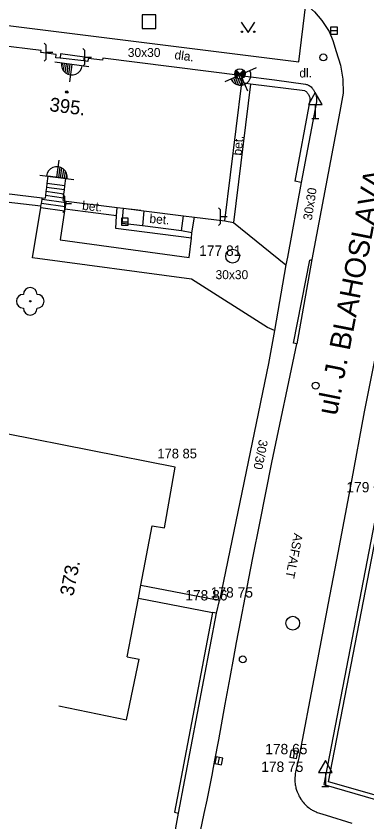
# Model space of a CAD drawing. Extents: x -538441 to -536770, y -1181008 to -1179809.
# Drawn here: x -537929.5 to -537904.1, y -1180678.1 to -1180619.8 of the extents above; entities that cross this region are included whole.
import ezdxf

# ---------------------------------------------------------------- set-up
doc = ezdxf.new("R2010")
doc.units = 0
for name, color, linetype in [('Vrstva 10', 7, 'Continuous'), ('Vrstva 11', 7, 'Continuous'), ('Vrstva 17', 7, 'Continuous'), ('Vrstva 22', 7, 'Continuous'), ('Vrstva 26', 7, 'Continuous'), ('Vrstva 27', 7, 'Continuous'), ('Vrstva 28', 7, 'Continuous'), ('Vrstva 31', 7, 'Continuous'), ('Vrstva 34', 7, 'Continuous'), ('Vrstva 36', 7, 'Continuous'), ('Vrstva 37', 7, 'Continuous'), ('Vrstva 39', 7, 'Continuous'), ('Vrstva 4', 7, 'Continuous'), ('Vrstva 40', 7, 'Continuous'), ('Vrstva 47', 7, 'Continuous'), ('Vrstva 49', 7, 'Continuous'), ('Vrstva 5', 7, 'Continuous'), ('Vrstva 6', 7, 'Continuous'), ('Vrstva 7', 7, 'Continuous'), ('Vrstva 8', 7, 'Continuous')]:
    doc.layers.add(name, color=color, linetype=linetype)

msp = doc.modelspace()

# ---------------------------------------------------------------- linework, layer by layer
at = {"layer": 'Vrstva 10'}
for p, q in [((-537905.81, -1180625.34), (-537906.04, -1180626.67)), ((-537906.04, -1180626.67), (-537908.08, -1180637.38)), ((-537909.41, -1180643.45), (-537908.22, -1180637.43)), ((-537908.08, -1180637.38), (-537909.16, -1180643.49)), ((-537908.22, -1180637.43), (-537908.08, -1180637.38)), ((-537902.05, -1180637.145), (-537904.27, -1180648.43)), ((-537910.975, -1180652.088), (-537909.16, -1180643.49)), ((-537909.16, -1180643.49), (-537909.41, -1180643.45)), ((-537904.27, -1180648.43), (-537905.23, -1180653.525)), ((-537905.23, -1180653.525), (-537906.19, -1180658.62)), ((-537906.19, -1180658.62), (-537906.88, -1180662.271)), ((-537912.91, -1180661.87), (-537912.347, -1180658.997)), ((-537906.88, -1180662.271), (-537907.919, -1180667.746)), ((-537907.919, -1180667.746), (-537908.96, -1180673.22)), ((-537914.825, -1180672.169), (-537914.351, -1180669.593))]:
    msp.add_line(p, q, dxfattribs=at)
for points in [[(-537908.51, -1180618.89), (-537907.885, -1180619.439), (-537907.342, -1180620.069), (-537906.82, -1180620.88), (-537906.542, -1180621.524), (-537906.3, -1180622.32)], [(-537906.3, -1180622.32), (-537905.998, -1180623.301), (-537905.834, -1180624.314), (-537905.81, -1180625.34)], [(-537912.347, -1180658.997), (-537911.851, -1180656.484), (-537910.975, -1180652.088)], [(-537914.351, -1180669.593), (-537913.997, -1180667.661), (-537913.731, -1180666.212), (-537913.529, -1180665.126), (-537913.223, -1180663.497), (-537912.91, -1180661.87)], [(-537916.52, -1180680.52), (-537916.15, -1180678.802), (-537915.877, -1180677.514), (-537915.676, -1180676.547), (-537915.527, -1180675.821), (-537915.31, -1180674.731), (-537915.204, -1180674.186), (-537915.1, -1180673.64), (-537914.825, -1180672.169)], [(-537908.96, -1180673.22), (-537908.992, -1180673.381), (-537909.056, -1180673.661), (-537909.157, -1180674.081), (-537909.205, -1180674.29), (-537909.25, -1180674.5), (-537909.275, -1180674.645), (-537909.292, -1180674.781), (-537909.302, -1180674.908), (-537909.306, -1180675.027), (-537909.304, -1180675.139), (-537909.298, -1180675.243), (-537909.288, -1180675.341), (-537909.275, -1180675.433), (-537909.26, -1180675.519), (-537909.243, -1180675.6), (-537909.225, -1180675.675), (-537909.205, -1180675.746), (-537909.184, -1180675.812), (-537909.14, -1180675.936), (-537909.096, -1180676.043), (-537909.052, -1180676.138), (-537909.01, -1180676.22), (-537908.971, -1180676.292), (-537908.934, -1180676.355), (-537908.866, -1180676.464), (-537908.81, -1180676.546), (-537908.765, -1180676.607), (-537908.695, -1180676.699), (-537908.62, -1180676.79), (-537908.575, -1180676.842), (-537908.531, -1180676.889), (-537908.488, -1180676.933), (-537908.404, -1180677.011), (-537908.324, -1180677.078), (-537908.249, -1180677.136), (-537908.177, -1180677.185), (-537908.109, -1180677.228), (-537908.045, -1180677.265), (-537907.985, -1180677.297), (-537907.87, -1180677.352), (-537907.768, -1180677.396), (-537907.679, -1180677.43), (-537907.519, -1180677.485), (-537907.275, -1180677.56), (-537907.026, -1180677.635), (-537905.175, -1180678.209)]]:
    msp.add_lwpolyline(points, dxfattribs=at)
at = {"layer": 'Vrstva 11'}
for p, q in [((-537944.15, -1180618.63), (-537924.88, -1180621.1)), ((-537909.01, -1180623.06), (-537908.51, -1180618.89)), ((-537924.88, -1180621.1), (-537909.01, -1180623.06)), ((-537912.526, -1180624.676), (-537913.75, -1180634.71)), ((-537908.84, -1180631.81), (-537909.85, -1180637.22)), ((-537927.724, -1180633.532), (-537939.86, -1180632.06)), ((-537926.024, -1180632.345), (-537927.323, -1180632.166)), ((-537925.988, -1180632.048), (-537927.287, -1180631.869)), ((-537926.098, -1180632.94), (-537927.397, -1180632.761)), ((-537926.061, -1180632.643), (-537927.36, -1180632.464)), ((-537925.968, -1180633.564), (-537927.69, -1180633.327)), ((-537925.917, -1180633.269), (-537927.641, -1180633.031)), ((-537927.739, -1180633.623), (-537926.02, -1180633.86)), ((-537926.02, -1180633.86), (-537926.32, -1180635.97)), ((-537922.231, -1180634.227), (-537926, -1180633.747)), ((-537920.257, -1180633.854), (-537920.365, -1180634.958)), ((-537917.52, -1180635.32), (-537917.378, -1180634.215)), ((-537916.79, -1180635.46), (-537916.596, -1180634.313)), ((-537914.39, -1180634.59), (-537913.75, -1180634.71)), ((-537913.75, -1180634.71), (-537909.948, -1180637.782)), ((-537916.81, -1180635.85), (-537922.28, -1180635.13)), ((-537916.79, -1180635.46), (-537917.52, -1180635.32)), ((-537916.98, -1180637.23), (-537916.81, -1180635.85)), ((-537916.81, -1180635.85), (-537916.79, -1180635.46)), ((-537926.32, -1180635.97), (-537916.98, -1180637.23)), ((-537916.8, -1180638.8), (-537928.34, -1180637.26)), ((-537911.3, -1180642.3), (-537916.8, -1180638.8)), ((-537910.78, -1180642.53), (-537911.3, -1180642.3)), ((-537910.78, -1180642.53), (-537911.22, -1180644.92)), ((-537911.22, -1180644.92), (-537914.76, -1180662.08)), ((-537920.478, -1180660.973), (-537915.054, -1180662.022)), ((-537920.659, -1180661.913), (-537915.275, -1180662.954))]:
    msp.add_line(p, q, dxfattribs=at)
for points in [[(-537924.602, -1180623.002), (-537924.57, -1180622.72), (-537926.3, -1180622.5), (-537926.335, -1180622.806)], [(-537928.34, -1180637.26), (-537927.739, -1180633.623), (-537927.724, -1180633.532), (-537927.69, -1180633.327), (-537927.641, -1180633.031), (-537927.624, -1180632.925)], [(-537925.896, -1180633.148), (-537925.917, -1180633.269), (-537925.968, -1180633.564), (-537926, -1180633.747), (-537926.02, -1180633.86)], [(-537922.28, -1180635.13), (-537922.231, -1180634.227), (-537922.198, -1180633.611)], [(-537917.52, -1180635.32), (-537920.365, -1180634.958), (-537921.84, -1180634.77), (-537921.728, -1180633.67)], [(-537909.85, -1180637.22), (-537909.948, -1180637.782), (-537910.78, -1180642.53)]]:
    msp.add_lwpolyline(points, dxfattribs=at)
at = {"layer": 'Vrstva 17'}
for p, q in [((-537913.664, -1180623.961), (-537913.467, -1180623.763)), ((-537913.661, -1180623.887), (-537913.502, -1180623.728)), ((-537913.656, -1180624.023), (-537913.431, -1180623.799)), ((-537913.639, -1180624.077), (-537913.396, -1180623.834)), ((-537913.633, -1180623.788), (-537913.537, -1180623.693)), ((-537913.616, -1180624.125), (-537913.361, -1180623.869)), ((-537913.588, -1180624.167), (-537913.325, -1180623.905)), ((-537913.555, -1180624.205), (-537913.025, -1180623.675)), ((-537913.555, -1180623.675), (-537913.025, -1180624.205)), ((-537913.255, -1180623.975), (-537912.992, -1180623.713)), ((-537913.219, -1180624.011), (-537912.964, -1180623.755)), ((-537913.184, -1180624.046), (-537912.941, -1180623.803)), ((-537913.149, -1180624.081), (-537912.924, -1180623.857)), ((-537913.113, -1180624.117), (-537912.916, -1180623.919)), ((-537913.078, -1180624.152), (-537912.919, -1180623.993)), ((-537913.043, -1180624.187), (-537912.947, -1180624.092))]:
    msp.add_line(p, q, dxfattribs=at)
msp.add_circle((-537913.29, -1180623.94), 0.375, dxfattribs=at)
at = {"layer": 'Vrstva 22'}
msp.add_circle((-537928.5, -1180640.41), 0.05, dxfattribs=at)
for centre, start, end in [((-537928.5, -1180639.91), 0, 180), ((-537929, -1180640.41), 90, 270), ((-537928, -1180640.41), 270, 90), ((-537928.5, -1180640.91), 180, 0)]:
    msp.add_arc(centre, 0.5, start, end, dxfattribs=at)
at = {"layer": 'Vrstva 26'}
msp.add_lwpolyline([(-537920.39, -1180620.66), (-537919.39, -1180620.66), (-537919.39, -1180619.66), (-537920.39, -1180619.66)], close=True, dxfattribs=at)
at = {"layer": 'Vrstva 27'}
for p, q in [((-537906.71, -1180620.81), (-537906.21, -1180620.81)), ((-537927.48, -1180621.728), (-537927.338, -1180621.87)), ((-537927.338, -1180622.87), (-537927.338, -1180621.87)), ((-537927.338, -1180622.37), (-537926.85, -1180622.37)), ((-537924.69, -1180622.098), (-537924.548, -1180622.24)), ((-537924.548, -1180623.24), (-537924.548, -1180622.24)), ((-537927.48, -1180623.01), (-537927.338, -1180622.87)), ((-537924.548, -1180622.74), (-537924.06, -1180622.74)), ((-537924.69, -1180623.38), (-537924.548, -1180623.24)), ((-537926.14, -1180632.688), (-537925.998, -1180632.83)), ((-537925.998, -1180633.83), (-537925.998, -1180632.83)), ((-537925.998, -1180633.33), (-537925.51, -1180633.33)), ((-537926.14, -1180633.97), (-537925.998, -1180633.83)), ((-537914.85, -1180633.638), (-537914.708, -1180633.78)), ((-537914.708, -1180634.78), (-537914.708, -1180633.78)), ((-537921.89, -1180634.65), (-537921.39, -1180634.65)), ((-537914.708, -1180634.28), (-537914.22, -1180634.28)), ((-537914.85, -1180634.92), (-537914.708, -1180634.78)), ((-537909.338, -1180672.978), (-537909.432, -1180673.47)), ((-537914.868, -1180673.94), (-537914.774, -1180673.45))]:
    msp.add_line(p, q, dxfattribs=at)
for points in [[(-537906.71, -1180621.06), (-537906.21, -1180621.06), (-537906.21, -1180620.56), (-537906.71, -1180620.56)], [(-537921.89, -1180634.9), (-537921.39, -1180634.9), (-537921.39, -1180634.4), (-537921.89, -1180634.4)], [(-537909.584, -1180672.932), (-537909.677, -1180673.423), (-537909.186, -1180673.516), (-537909.093, -1180673.025)], [(-537914.623, -1180673.988), (-537914.528, -1180673.497), (-537915.019, -1180673.402), (-537915.114, -1180673.893)]]:
    msp.add_lwpolyline(points, close=True, dxfattribs=at)
for centre in [(-537913.82, -1180637.14), (-537909.46, -1180663.73)]:
    msp.add_circle(centre, 0.5, dxfattribs=at)
at = {"layer": 'Vrstva 28'}
for centre in [(-537907.79, -1180646.52), (-537913.08, -1180666.35)]:
    msp.add_circle(centre, 0.25, dxfattribs=at)
at = {"layer": 'Vrstva 31'}
msp.add_circle((-537907.24, -1180622.75), 0.25, dxfattribs=at)
at = {"layer": 'Vrstva 34'}
for p, q in [((-537907.824, -1180626.156), (-537907.824, -1180627.174)), ((-537908.074, -1180627.174), (-537907.574, -1180627.174)), ((-537907.09, -1180674.541), (-537907.09, -1180675.559)), ((-537907.34, -1180675.559), (-537906.84, -1180675.559))]:
    msp.add_line(p, q, dxfattribs=at)
for points in [[(-537908.324, -1180626.156), (-537907.324, -1180626.156), (-537907.824, -1180625.29)], [(-537907.59, -1180674.541), (-537906.59, -1180674.541), (-537907.09, -1180673.675)]]:
    msp.add_lwpolyline(points, close=True, dxfattribs=at)
at = {"layer": 'Vrstva 36'}
msp.add_lwpolyline([(-537913.199, -1180620.189), (-537912.699, -1180620.939), (-537912.199, -1180620.189)], dxfattribs=at)
for centre in [(-537913.149, -1180620.889), (-537912.25, -1180620.889)]:
    msp.add_circle(centre, 0.05, dxfattribs=at)
at = {"layer": 'Vrstva 37'}
for p, q in [((-537924.248, -1180623.427), (-537926.726, -1180623.103)), ((-537926.181, -1180623.174), (-537926.217, -1180623.451)), ((-537926.043, -1180623.192), (-537926.109, -1180623.695)), ((-537925.903, -1180623.211), (-537925.985, -1180623.835)), ((-537925.765, -1180623.229), (-537925.856, -1180623.927)), ((-537925.625, -1180623.247), (-537925.721, -1180623.986)), ((-537925.487, -1180623.265), (-537925.65, -1180624.511)), ((-537912.104, -1180623.51), (-537914.396, -1180624.51)), ((-537913.763, -1180624.234), (-537913.56, -1180624.699)), ((-537913.635, -1180624.178), (-537913.383, -1180624.755)), ((-537913.507, -1180624.122), (-537913.225, -1180624.767)), ((-537913.378, -1180624.066), (-537913.08, -1180624.749)), ((-537913.25, -1180624.01), (-537912.747, -1180625.163)), ((-537913.892, -1180624.29), (-537913.78, -1180624.545)), ((-537926.572, -1180631.427), (-537926.409, -1180630.181)), ((-537926.434, -1180631.445), (-537926.338, -1180630.706)), ((-537926.294, -1180631.463), (-537926.203, -1180630.765)), ((-537926.156, -1180631.481), (-537926.074, -1180630.857)), ((-537926.016, -1180631.5), (-537925.95, -1180630.997)), ((-537925.878, -1180631.518), (-537925.842, -1180631.241)), ((-537927.811, -1180631.265), (-537925.333, -1180631.589))]:
    msp.add_line(p, q, dxfattribs=at)
for centre, start, end in [((-537925.488, -1180623.273), 171.92788, 353.17392), ((-537913.247, -1180624.017), 202.95771, 24.20376), ((-537926.571, -1180631.419), 351.92788, 173.17392)]:
    msp.add_arc(centre, 0.75, start, end, dxfattribs=at)
at = {"layer": 'Vrstva 39'}
for radius in [0.09, 0.0398]:
    msp.add_circle((-537925.85, -1180625.252), radius, dxfattribs=at)
at = {"layer": 'Vrstva 5'}
for p, q in [((-537927.71, -1180622.25), (-537937.79, -1180621.01)), ((-537927.729, -1180622.404), (-537927.71, -1180622.25)), ((-537926.62, -1180622.54), (-537927.729, -1180622.404)), ((-537926.65, -1180622.77), (-537926.62, -1180622.54)), ((-537924.31, -1180622.82), (-537924.334, -1180623.032)), ((-537923.25, -1180622.94), (-537924.31, -1180622.82)), ((-537923.23, -1180622.8), (-537923.25, -1180622.94)), ((-537913.09, -1180624.07), (-537923.23, -1180622.8)), ((-537925.922, -1180631.512), (-537927.222, -1180631.342)), ((-537917.98, -1180652.42), (-537930.21, -1180650)), ((-537918.76, -1180656.83), (-537917.98, -1180652.42)), ((-537920.478, -1180660.973), (-537919.646, -1180656.673)), ((-537919.646, -1180656.673), (-537918.76, -1180656.83)), ((-537920.659, -1180661.913), (-537920.478, -1180660.973)), ((-537921.48, -1180666.155), (-537920.659, -1180661.913)), ((-537921.48, -1180666.155), (-537920.6, -1180666.34)), ((-537921.52, -1180670.73), (-537920.6, -1180666.34)), ((-537926.414, -1180669.704), (-537921.52, -1180670.73))]:
    msp.add_line(p, q, dxfattribs=at)
for points in [[(-537924.334, -1180623.032), (-537924.602, -1180623.002), (-537926.335, -1180622.806), (-537926.65, -1180622.77)], [(-537914.39, -1180634.59), (-537913.155, -1180624.596), (-537913.09, -1180624.07)], [(-537939.18, -1180631.53), (-537927.624, -1180632.925), (-537927.42, -1180632.95)], [(-537927.222, -1180631.342), (-537927.287, -1180631.869), (-537927.323, -1180632.166), (-537927.36, -1180632.464), (-537927.397, -1180632.761), (-537927.42, -1180632.95)], [(-537926.12, -1180633.12), (-537926.098, -1180632.94), (-537926.061, -1180632.643), (-537926.024, -1180632.345), (-537925.988, -1180632.048), (-537925.922, -1180631.512)], [(-537926.12, -1180633.12), (-537925.896, -1180633.148), (-537922.198, -1180633.611), (-537921.728, -1180633.67), (-537920.257, -1180633.854), (-537917.378, -1180634.215), (-537916.596, -1180634.313), (-537914.39, -1180634.59)]]:
    msp.add_lwpolyline(points, dxfattribs=at)
at = {"layer": 'Vrstva 6'}
msp.add_line((-537921.31, -1180633.72), (-537920.47, -1180633.82), dxfattribs=at)
at = {"layer": 'Vrstva 7'}
for p, q in [((-537908.212, -1180625.871), (-537909.312, -1180631.721)), ((-537903.52, -1180656.41), (-537907.21, -1180675.42)), ((-537906.863, -1180675.208), (-537903.284, -1180656.766)), ((-537915.275, -1180662.954), (-537918.045, -1180677.424)), ((-537907.21, -1180675.42), (-537876.93, -1180684.15)), ((-537876.853, -1180683.86), (-537906.863, -1180675.208))]:
    msp.add_line(p, q, dxfattribs=at)
for points in [[(-537913.09, -1180624.07), (-537910.775, -1180624.36), (-537908.54, -1180624.68), (-537908.449, -1180624.7), (-537908.407, -1180624.715), (-537908.367, -1180624.732), (-537908.328, -1180624.75), (-537908.292, -1180624.771), (-537908.257, -1180624.792), (-537908.192, -1180624.84), (-537908.134, -1180624.89), (-537908.082, -1180624.942), (-537908.036, -1180624.995), (-537907.994, -1180625.047), (-537907.958, -1180625.098), (-537907.926, -1180625.147), (-537907.898, -1180625.195), (-537907.85, -1180625.288), (-537907.814, -1180625.372), (-537907.787, -1180625.446), (-537907.767, -1180625.512), (-537907.752, -1180625.57), (-537907.742, -1180625.62), (-537907.73, -1180625.708), (-537907.726, -1180625.773), (-537907.726, -1180625.821), (-537907.73, -1180625.892), (-537907.74, -1180625.96)], [(-537908.584, -1180625.176), (-537912.526, -1180624.676), (-537913.155, -1180624.596)], [(-537908.584, -1180625.176), (-537908.536, -1180625.184), (-537908.524, -1180625.192), (-537908.492, -1180625.215), (-537908.461, -1180625.242), (-537908.433, -1180625.269), (-537908.404, -1180625.303), (-537908.377, -1180625.337), (-537908.355, -1180625.368), (-537908.335, -1180625.399), (-537908.319, -1180625.426), (-537908.284, -1180625.493), (-537908.26, -1180625.549), (-537908.242, -1180625.598), (-537908.229, -1180625.642), (-537908.22, -1180625.677), (-537908.216, -1180625.7), (-537908.208, -1180625.755), (-537908.206, -1180625.788), (-537908.206, -1180625.807), (-537908.208, -1180625.843), (-537908.212, -1180625.871)], [(-537907.74, -1180625.96), (-537908.84, -1180631.81), (-537909.312, -1180631.721)], [(-537914.76, -1180662.08), (-537915.054, -1180662.022)], [(-537917.75, -1180677.48), (-537914.98, -1180663.01)], [(-537914.98, -1180663.01), (-537915.275, -1180662.954)], [(-537918.045, -1180677.424), (-537917.75, -1180677.48)]]:
    msp.add_lwpolyline(points, dxfattribs=at)
at = {"layer": 'Vrstva 8'}
for p, q in [((-537914.98, -1180663.01), (-537914.76, -1180662.08)), ((-537918.311, -1180680.696), (-537917.75, -1180677.48))]:
    msp.add_line(p, q, dxfattribs=at)

# ---------------------------------------------------------------- texts
at = {"layer": 'Vrstva 4'}
for s, height, p in [('177 81 ', 0.75, (-537916.25, -1180637.12)), ('178 85 ', 0.7, (-537919.273, -1180651.79)), ('179 09 ', 0.75, (-537905.57, -1180654.25)), ('178 86 ', 0.75, (-537917.26, -1180662.08)), ('178 75 ', 0.75, (-537915.41, -1180661.87)), ('178 65 ', 0.75, (-537911.46, -1180673.22)), ('178 75 ', 0.75, (-537911.75, -1180674.5))]:
    msp.add_text(s, height=height, dxfattribs=at).set_placement(p)
at = {"layer": 'Vrstva 40'}
for s, p in [('30x30', (-537921.423, -1180622.716)), ('dl.', (-537908.981, -1180624.2)), ('30x30', (-537915.057, -1180638.81))]:
    msp.add_text(s, height=0.65, dxfattribs=at).set_placement(p)
for s, rotation, p in [('dla.', 353.01743, (-537918.064, -1180622.869)), ('bet.', 85, (-537913.168, -1180629.878)), ('30x30', 81.18337, (-537908.074, -1180634.579)), ('bet.', 355, (-537924.754, -1180633.789)), ('bet.', 355, (-537919.874, -1180634.731)), ('30/30', 258.89695, (-537911.893, -1180650.389)), ('ASFALT', 258.87143, (-537909.359, -1180657.177))]:
    msp.add_text(s, height=0.65, rotation=rotation, dxfattribs=at).set_placement(p)
at = {"layer": 'Vrstva 47'}
for s, rotation, p in [('395.', 352.7551, (-537927.144, -1180626.631)), ('373.', 79.05308, (-537925.379, -1180661.815))]:
    msp.add_text(s, height=1, rotation=rotation, dxfattribs=at).set_placement(p)
at = {"layer": 'Vrstva 49'}
msp.add_text('ul. J. BLAHOSLAVA', height=1.5, rotation=78.87081, dxfattribs=at).set_placement((-537906.267, -1180648.738))

doc.saveas('drawing.dxf')
